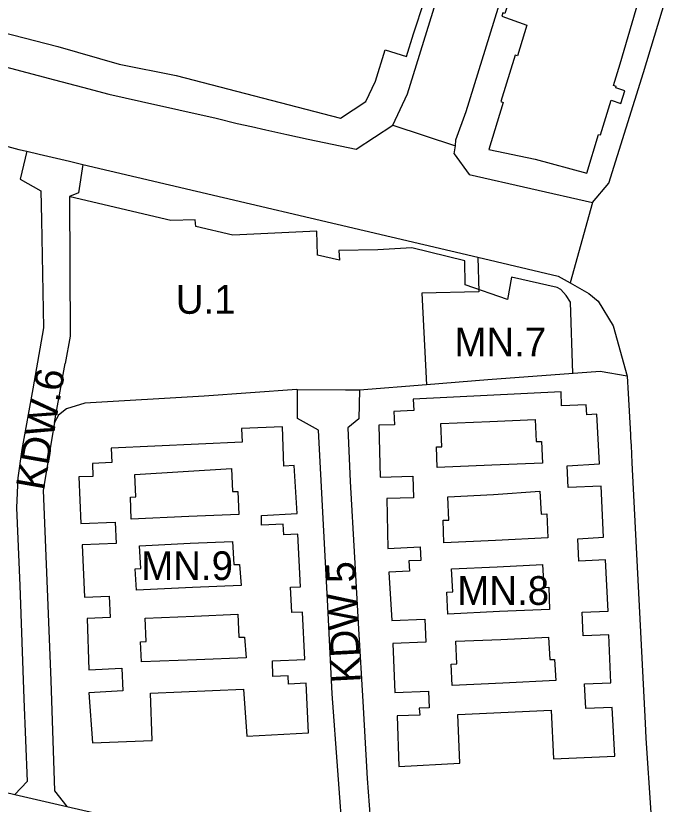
# Model space of a CAD drawing. Extents: x 7419601 to 7420547, y 5548907 to 5549873.
# Drawn here: x 7420129.8 to 7420244.8, y 5549175.5 to 5549312.7 of the extents above; entities that cross this region are included whole.
import ezdxf

# ---------------------------------------------------------------- set-up
doc = ezdxf.new("R2010")
doc.units = 0
for name, color, linetype in [('LIN_linie_rozgraniczajace', 7, 'Continuous'), ('LIN_nieprzekraczalna linia zabudowy', 7, 'Continuous'), ('LIN_obowiązująca linia zabudowy', 7, 'Continuous'), ('TXT_opisy_przeznaczen', 7, 'Continuous')]:
    doc.layers.add(name, color=color, linetype=linetype)

msp = doc.modelspace()

# ---------------------------------------------------------------- linework, layer by layer
at = {"layer": 'LIN_linie_rozgraniczajace'}
for p, q in [((7420195.45, 5549293.66), (7420206.36, 5549290.05)), ((7420133.94, 5549288.58), (7420139.19, 5549287.35)), ((7420230.19, 5549280.18), (7420226.34, 5549266.19)), ((7420136.57, 5549241.92), (7420138.43, 5549252.21)), ((7420187.25, 5549247.55), (7420178.89, 5549247.63)), ((7420189.69, 5549247.52), (7420187.25, 5549247.55))]:
    msp.add_line(p, q, dxfattribs=at)
for points in [[(7420195.45, 5549293.66), (7420198.05, 5549299.11), (7420211.79, 5549343.46), (7420248.32, 5549462.89), (7420246.2, 5549466.76), (7420241.79, 5549468.35)], [(7420206.16, 5549288.67), (7420206.36, 5549290.05), (7420206.43, 5549291.1), (7420208.23, 5549296.04), (7420216.58, 5549323.05), (7420224.94, 5549350.06), (7420234.81, 5549383.04), (7420242.46, 5549407.37), (7420247.93, 5549426.27), (7420253.33, 5549444.88), (7420260.19, 5549466.67)], [(7420233.06, 5549283.54), (7420239.1, 5549302.78), (7420244.83, 5549321.8), (7420250.62, 5549340.99), (7420256.57, 5549360.03)], [(7420103.37, 5549309.87), (7420124.03, 5549304.85), (7420136.57, 5549301.5), (7420141.49, 5549300.23)], [(7420091.26, 5549300.02), (7420110.06, 5549294.92), (7420130.41, 5549289.41), (7420131.78, 5549289.09), (7420133.94, 5549288.58)], [(7420141.49, 5549300.23), (7420146.07, 5549299.05), (7420151.73, 5549297.77), (7420164.73, 5549294.88), (7420168.35, 5549293.93), (7420170.86, 5549293.38), (7420173.36, 5549292.84), (7420177.04, 5549292.02), (7420180.71, 5549291.2), (7420189.09, 5549289.47)], [(7420189.09, 5549289.47), (7420195.45, 5549293.66)], [(7420131.78, 5549289.09), (7420130.64, 5549284.24), (7420134.19, 5549282.23), (7420134.3, 5549277.16), (7420134.49, 5549267.77), (7420134.69, 5549258.38), (7420132.79, 5549247.8), (7420130.9, 5549237.22), (7420130.22, 5549232.3), (7420130, 5549227.05), (7420130.53, 5549213.54), (7420130.9, 5549203.7), (7420131.27, 5549193.86), (7420131.83, 5549179.46), (7420129.69, 5549177.2)], [(7420206.16, 5549288.67), (7420208.74, 5549285.04), (7420219.47, 5549282.61), (7420230.19, 5549280.18), (7420233.06, 5549283.54)], [(7420139.19, 5549287.35), (7420141.52, 5549286.8), (7420210.25, 5549270.67)], [(7420141.52, 5549286.8), (7420140.74, 5549281.86), (7420139.22, 5549281.25), (7420139.32, 5549256.95), (7420138.43, 5549252.21)], [(7420210.25, 5549270.67), (7420210.41, 5549264.62), (7420200.53, 5549264.39), (7420201.32, 5549248.48)], [(7420210.25, 5549270.67), (7420224.22, 5549267.4), (7420226.34, 5549266.19), (7420229.58, 5549264.35)], [(7420229.58, 5549264.35), (7420231.23, 5549263.02), (7420233.81, 5549258.72), (7420236.25, 5549249.99)], [(7420236.25, 5549249.99), (7420231.55, 5549250.78), (7420211.98, 5549249.36), (7420201.32, 5549248.48)], [(7420236.25, 5549249.99), (7420236.45, 5549246.97), (7420236.83, 5549239.86), (7420236.85, 5549239.28), (7420236.93, 5549237.9), (7420237.08, 5549234.89), (7420239.37, 5549189.63), (7420239.49, 5549187), (7420240.38, 5549174), (7420240.47, 5549173.13)], [(7420185.33, 5549166.5), (7420186.88, 5549168.03), (7420184.93, 5549194.71), (7420184.15, 5549209.97), (7420183.36, 5549225.24), (7420182.55, 5549240.59), (7420178.89, 5549242.63), (7420178.89, 5549247.63), (7420178.78, 5549247.66), (7420162.62, 5549246.51), (7420141.87, 5549245.26), (7420138.65, 5549244.31), (7420137.27, 5549243.18), (7420136.57, 5549241.92)], [(7420189.69, 5549247.52), (7420189.58, 5549242.57), (7420187.64, 5549240.97)], [(7420201.32, 5549248.48), (7420189.69, 5549247.52)], [(7420136.57, 5549241.92), (7420134.61, 5549230.15), (7420135.42, 5549210.09), (7420135.93, 5549197.02), (7420136.56, 5549177.82), (7420138.71, 5549175.15), (7420163.31, 5549169.47)], [(7420187.64, 5549240.97), (7420188.02, 5549231.63), (7420188.8, 5549218.43), (7420189.5, 5549206.03), (7420190.26, 5549193.39), (7420190.99, 5549179.98), (7420191.5, 5549173.05), (7420191.88, 5549168.04)], [(7420083.48, 5549188.06), (7420086.58, 5549187.35), (7420108.79, 5549182.25), (7420129.69, 5549177.2), (7420138.71, 5549175.15)]]:
    msp.add_lwpolyline(points, dxfattribs=at)
at = {"layer": 'LIN_nieprzekraczalna linia zabudowy'}
for points in [[(7420247.52, 5549405.31), (7420235.77, 5549366.6), (7420229.82, 5549347.39), (7420224.09, 5549328.34), (7420223.06, 5549324.95), (7420219.23, 5549326.13), (7420216.19, 5549316.67), (7420215.86, 5549316.78), (7420215.52, 5549315.99), (7420215.9, 5549315.85), (7420214.98, 5549313.07), (7420214.64, 5549313.19), (7420214.45, 5549312.63), (7420218.8, 5549311.04), (7420217.16, 5549305.69), (7420216.75, 5549305.81), (7420214.25, 5549297.76), (7420214.69, 5549297.61), (7420212.19, 5549289.43)], [(7420190.75, 5549297.75), (7420192.45, 5549301.3), (7420194.13, 5549306.73), (7420197.85, 5549305.57), (7420199.09, 5549309.54), (7420202.92, 5549321.17)], [(7420229.23, 5549285.31), (7420231.28, 5549292.04), (7420231.62, 5549291.94), (7420233.48, 5549297.98), (7420235.16, 5549297.43), (7420235.87, 5549299.63), (7420234.28, 5549300.14), (7420234.35, 5549300.38), (7420233.87, 5549300.54), (7420235.01, 5549304.3), (7420239.92, 5549321.03)], [(7420105.79, 5549315.41), (7420137.18, 5549307.31)], [(7420137.18, 5549307.31), (7420147.85, 5549304.25), (7420157.75, 5549302.3), (7420186.35, 5549294.85), (7420190.75, 5549297.75)], [(7420212.19, 5549289.43), (7420220.23, 5549287.7), (7420229.23, 5549285.31)], [(7420208.06, 5549265.89), (7420208.01, 5549270.05), (7420198.78, 5549272.33), (7420192.86, 5549271.93), (7420186.09, 5549271.82), (7420186.17, 5549270.16), (7420182.36, 5549271.05), (7420182.23, 5549275.21), (7420167.61, 5549274.52), (7420161.19, 5549276.02), (7420161.07, 5549277.18), (7420156.86, 5549277.04), (7420139.33, 5549281.15)], [(7420226.82, 5549250.44), (7420226.36, 5549262.84), (7420225.66, 5549264.03), (7420224.73, 5549265.03), (7420224.04, 5549265.42), (7420216.14, 5549267.22), (7420215.42, 5549263.3), (7420208.06, 5549265.89)]]:
    msp.add_lwpolyline(points, dxfattribs=at)
at = {"layer": 'LIN_obowiązująca linia zabudowy'}
for p, q in [((7420224.78, 5549247.28), (7420199.01, 5549245.99)), ((7420199.01, 5549245.99), (7420199.11, 5549244.03)), ((7420224.82, 5549244.79), (7420224.78, 5549247.28)), ((7420229.13, 5549245.02), (7420224.82, 5549244.79)), ((7420229.22, 5549243.26), (7420229.13, 5549245.02)), ((7420199.11, 5549244.03), (7420195.65, 5549243.86)), ((7420195.65, 5549243.86), (7420195.77, 5549241.5)), ((7420230.98, 5549243.36), (7420229.22, 5549243.26)), ((7420231.45, 5549234.7), (7420230.98, 5549243.36)), ((7420176.24, 5549241.14), (7420169.12, 5549240.85)), ((7420169.12, 5549240.85), (7420169.22, 5549238.47)), ((7420176.51, 5549234.35), (7420176.24, 5549241.14)), ((7420195.77, 5549241.5), (7420193.04, 5549241.43)), ((7420193.04, 5549241.43), (7420193.29, 5549232.4)), ((7420169.22, 5549238.47), (7420146.47, 5549237.44)), ((7420146.47, 5549237.44), (7420146.58, 5549234.95)), ((7420146.58, 5549234.95), (7420143.18, 5549234.79)), ((7420143.18, 5549234.79), (7420143.28, 5549232.51)), ((7420178.27, 5549234.42), (7420176.51, 5549234.35)), ((7420178.82, 5549226.07), (7420178.27, 5549234.42)), ((7420225.81, 5549234.38), (7420231.45, 5549234.7)), ((7420226.01, 5549230.61), (7420225.81, 5549234.38)), ((7420143.28, 5549232.51), (7420140.84, 5549232.48)), ((7420140.84, 5549232.48), (7420141.18, 5549224.33)), ((7420193.29, 5549232.4), (7420198.97, 5549232.56)), ((7420198.97, 5549232.56), (7420199.08, 5549228.81)), ((7420231.7, 5549230.86), (7420226.01, 5549230.61)), ((7420232.11, 5549221.95), (7420231.7, 5549230.86)), ((7420199.08, 5549228.81), (7420194.4, 5549228.67)), ((7420194.4, 5549228.67), (7420194.6, 5549220)), ((7420172.6, 5549224.07), (7420172.62, 5549225.77)), ((7420172.62, 5549225.77), (7420178.82, 5549226.07)), ((7420141.18, 5549224.33), (7420147.15, 5549224.61)), ((7420147.15, 5549224.61), (7420147.3, 5549220.86)), ((7420176.39, 5549224.26), (7420172.6, 5549224.07)), ((7420176.49, 5549222.35), (7420176.39, 5549224.26)), ((7420178.95, 5549222.47), (7420176.49, 5549222.35)), ((7420179.41, 5549213.32), (7420178.95, 5549222.47)), ((7420227.66, 5549221.7), (7420232.11, 5549221.95)), ((7420227.86, 5549217.77), (7420227.66, 5549221.7)), ((7420147.3, 5549220.86), (7420141.39, 5549220.64)), ((7420141.39, 5549220.64), (7420141.83, 5549211.52)), ((7420194.6, 5549220), (7420200.25, 5549220.29)), ((7420200.25, 5549220.29), (7420200.37, 5549217.93)), ((7420200.37, 5549217.93), (7420198.28, 5549217.83)), ((7420198.28, 5549217.83), (7420198.37, 5549216.05)), ((7420232.48, 5549218.01), (7420227.86, 5549217.77)), ((7420232.93, 5549209.11), (7420232.48, 5549218.01)), ((7420198.37, 5549216.05), (7420194.79, 5549215.86)), ((7420194.79, 5549215.86), (7420195.27, 5549207.48)), ((7420177.68, 5549213.28), (7420179.41, 5549213.32)), ((7420177.91, 5549208.84), (7420177.68, 5549213.28)), ((7420141.83, 5549211.52), (7420146.11, 5549211.73)), ((7420146.11, 5549211.73), (7420146.28, 5549208)), ((7420228.4, 5549208.92), (7420232.93, 5549209.11)), ((7420146.28, 5549208), (7420142.29, 5549207.83)), ((7420142.29, 5549207.83), (7420142.59, 5549198.88)), ((7420179.73, 5549208.94), (7420177.91, 5549208.84)), ((7420180.16, 5549200.71), (7420179.73, 5549208.94)), ((7420195.27, 5549207.48), (7420201.03, 5549207.73)), ((7420201.03, 5549207.73), (7420201.19, 5549203.7)), ((7420228.57, 5549204.82), (7420228.4, 5549208.92)), ((7420233.07, 5549205.01), (7420228.57, 5549204.82)), ((7420233.42, 5549196.65), (7420233.07, 5549205.01)), ((7420201.19, 5549203.7), (7420195.47, 5549203.48)), ((7420195.47, 5549203.48), (7420195.84, 5549194.93)), ((7420174.5, 5549200.44), (7420180.16, 5549200.71)), ((7420174.57, 5549197.72), (7420174.5, 5549200.44)), ((7420142.59, 5549198.88), (7420148.33, 5549199.16)), ((7420148.33, 5549199.16), (7420148.49, 5549195.23)), ((7420177.28, 5549197.83), (7420174.57, 5549197.72)), ((7420177.34, 5549196.42), (7420177.28, 5549197.83)), ((7420228.85, 5549196.44), (7420233.42, 5549196.65)), ((7420148.49, 5549195.23), (7420142.59, 5549194.87)), ((7420153.29, 5549194.84), (7420169.5, 5549195.53)), ((7420169.5, 5549195.53), (7420170.04, 5549187.35)), ((7420180.41, 5549196.55), (7420177.34, 5549196.42)), ((7420180.77, 5549187.93), (7420180.41, 5549196.55)), ((7420229.03, 5549192.16), (7420228.85, 5549196.44)), ((7420142.59, 5549194.87), (7420143.23, 5549186.18)), ((7420153.56, 5549186.6), (7420153.29, 5549194.84)), ((7420195.84, 5549194.93), (7420201.68, 5549195.2)), ((7420201.68, 5549195.2), (7420201.81, 5549192.29)), ((7420201.81, 5549192.29), (7420200.08, 5549192.21)), ((7420200.08, 5549192.21), (7420200.14, 5549191)), ((7420206.77, 5549191.13), (7420223.04, 5549191.85)), ((7420207.12, 5549182.66), (7420206.77, 5549191.13)), ((7420223.04, 5549191.85), (7420223.45, 5549183.44)), ((7420233.63, 5549192.36), (7420229.03, 5549192.16)), ((7420234.09, 5549183.85), (7420233.63, 5549192.36)), ((7420200.14, 5549191), (7420196.21, 5549190.88)), ((7420196.21, 5549190.88), (7420196.54, 5549182.06)), ((7420170.04, 5549187.35), (7420180.77, 5549187.93)), ((7420143.23, 5549186.18), (7420153.56, 5549186.6)), ((7420223.45, 5549183.44), (7420234.09, 5549183.85)), ((7420196.54, 5549182.06), (7420207.12, 5549182.66))]:
    msp.add_line(p, q, dxfattribs=at)
for points in [[(7420203.19, 5549234.11), (7420203.04, 5549237.67), (7420203.97, 5549237.7), (7420203.8, 5549241.74), (7420212.34, 5549242.11), (7420220.22, 5549242.43), (7420220.4, 5549238.6), (7420221.32, 5549238.64), (7420221.52, 5549234.86), (7420212.71, 5549234.5)], [(7420149.96, 5549225.08), (7420149.81, 5549228.92), (7420150.77, 5549228.96), (7420150.58, 5549232.9), (7420167.38, 5549233.9), (7420167.57, 5549229.9), (7420168.51, 5549229.94), (7420168.68, 5549225.94), (7420159.96, 5549225.54)], [(7420204.36, 5549221.01), (7420204.2, 5549224.91), (7420205.22, 5549224.95), (7420205.06, 5549228.98), (7420212.96, 5549229.4), (7420221.07, 5549229.97), (7420221.27, 5549225.99), (7420222.25, 5549226.03), (7420222.46, 5549221.87), (7420213.34, 5549221.4)], [(7420150.84, 5549212.73), (7420150.62, 5549216.44), (7420151.6, 5549216.53), (7420151.41, 5549220.47), (7420160.19, 5549220.92), (7420167.54, 5549221.2), (7420167.8, 5549217.2), (7420168.8, 5549217.24), (7420169.05, 5549213.55), (7420160.58, 5549213.22)], [(7420205.06, 5549208.59), (7420204.84, 5549212.41), (7420205.93, 5549212.46), (7420205.69, 5549216.44), (7420213.6, 5549216.82), (7420221.53, 5549217.24), (7420221.76, 5549213.22), (7420222.61, 5549213.25), (7420222.75, 5549209.38), (7420214.04, 5549209.06)], [(7420151.74, 5549200.28), (7420151.58, 5549203.78), (7420152.53, 5549203.83), (7420152.34, 5549207.88), (7420160.87, 5549208.24), (7420168.52, 5549208.59), (7420168.68, 5549204.57), (7420169.68, 5549204.6), (7420169.93, 5549201), (7420161.32, 5549200.66)], [(7420205.78, 5549196.16), (7420205.63, 5549199.87), (7420206.63, 5549199.93), (7420206.45, 5549203.9), (7420214.26, 5549204.2), (7420222.57, 5549204.56), (7420222.78, 5549200.68), (7420223.62, 5549200.71), (7420223.83, 5549197.02), (7420214.59, 5549196.59)]]:
    msp.add_lwpolyline(points, close=True, dxfattribs=at)

# ---------------------------------------------------------------- texts
at = {"layer": 'TXT_opisy_przeznaczen'}
for s, p in [('U.1', (7420157.7, 5549260.83)), ('MN.7', (7420206.19, 5549253.43)), ('MN.9', (7420151.68, 5549214.51)), ('MN.8', (7420206.69, 5549210.19))]:
    msp.add_text(s, height=5, dxfattribs=at).set_placement(p)
for s, rotation, p in [('KDW.6', 80, (7420134.76, 5549229.94)), ('KDW.5', 93, (7420189.91, 5549196.73))]:
    msp.add_text(s, height=5, rotation=rotation, dxfattribs=at).set_placement(p)

doc.saveas('drawing.dxf')
